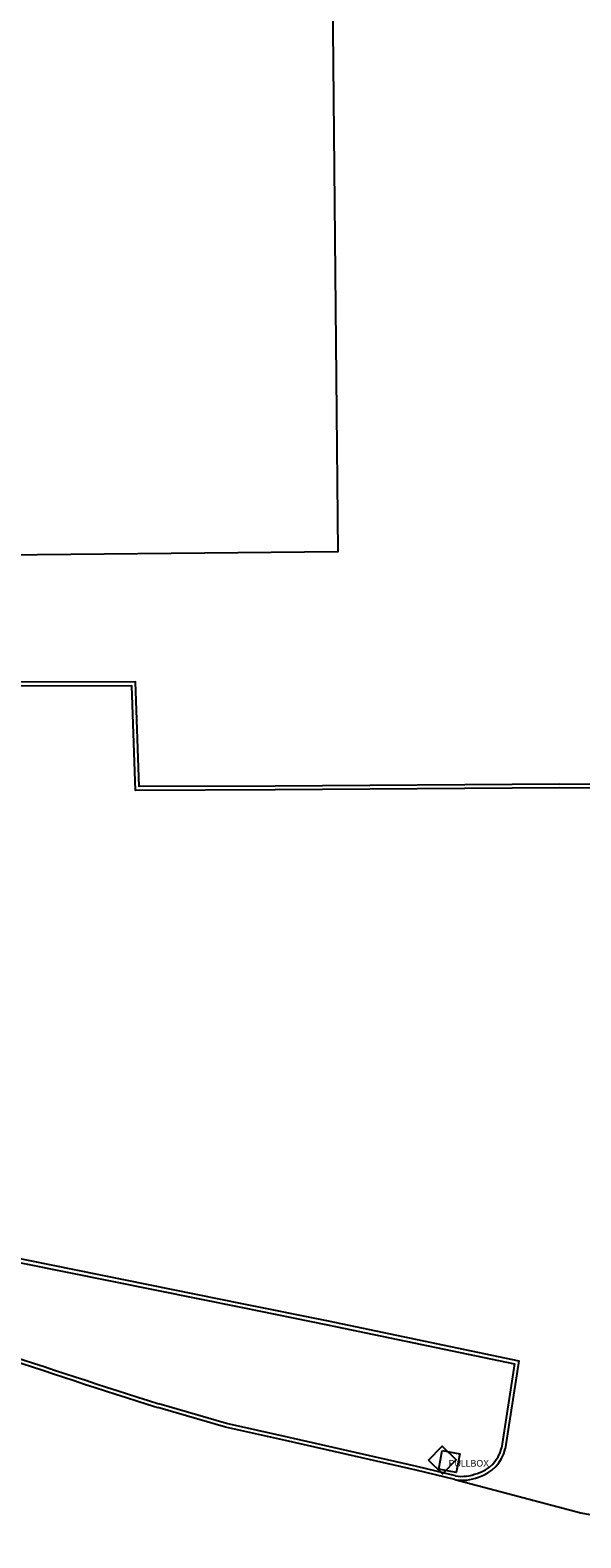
# Model space of a CAD drawing. Extents: x 2145380 to 2156929, y 139568 to 149130.
# Drawn here: x 2151125.7 to 2151210.1, y 145633.5 to 145864.8 of the extents above; entities that cross this region are included whole.
import ezdxf

# ---------------------------------------------------------------- set-up
doc = ezdxf.new("R2010")
doc.units = 0
for name, color, linetype in [('Default', 7, 'Continuous'), ('TOPO_Asphalt', 7, 'Continuous'), ('TOPO_Building', 7, 'Continuous'), ('TOPO_Curb Back', 7, 'Continuous'), ('TOPO_DRAIN_Inlet Grate', 7, 'Continuous'), ('TOPO_Power Pullbox', 7, 'Continuous')]:
    doc.layers.add(name, color=color, linetype=linetype)

# ---------------------------------------------------------------- blocks, each defined once
blk = doc.blocks.new('pulbox')
at = {"layer": 'Default'}
blk.add_lwpolyline([(-5.38, -0.01), (-0.02, 5.42), (5.4, 0.06), (0.05, -5.36), (-5.38, -0.01)], dxfattribs=at)
blk.add_text('PULLBOX', height=2.54, dxfattribs=at).set_placement((2.54, -2.54))

msp = doc.modelspace()

# ---------------------------------------------------------------- linework, layer by layer
at = {"layer": 'TOPO_Asphalt'}
msp.add_lwpolyline([(2151190.79, 145642.47), (2151210.13, 145637.38)], dxfattribs=at)
msp.add_arc((2151248.89, 145831.11), 197.58, 258.687, 271.7273, dxfattribs=at)
at = {"layer": 'TOPO_Building'}
msp.add_lwpolyline([(2151171.94, 145881.01), (2151172.88, 145784.76), (2151111.47, 145784.16), (2151111.23, 145808.23), (2151109.97, 145808.22), (2151109.28, 145880.07), (2151070.88, 145879.7), (2151071.52, 145813.5), (2151007.23, 145812.88), (2151006.64, 145873.96), (2150993.06, 145873.83), (2150992.7, 145910.67), (2151014.52, 145910.88), (2151014.53, 145909.77), (2151156.7, 145911.15), (2151156.99, 145880.87)], close=True, dxfattribs=at)
at = {"layer": 'TOPO_Curb Back'}
for points in [[(2151232.04, 145670.64), (2151232.85, 145679.69), (2151232.77, 145701.33), (2151232.73, 145721.64), (2151232.83, 145748.41), (2151206.88, 145748.55), (2151163.27, 145748.25), (2151141.84, 145748.16), (2151141.29, 145764.21), (2151114.56, 145764.17), (2151114.58, 145767.02)], [(2151232.64, 145670.63), (2151233.45, 145679.66), (2151233.37, 145701.33), (2151233.33, 145721.64), (2151233.43, 145749.01), (2151206.88, 145749.15), (2151163.26, 145748.85), (2151142.42, 145748.76), (2151141.87, 145764.81), (2151115.17, 145764.77), (2151115.18, 145767.01)], [(2151026.47, 145697.22), (2151026.29, 145695.56), (2151069.97, 145686.63), (2151117.91, 145677.02), (2151158.27, 145668.86), (2151171.27, 145666.22), (2151199.97, 145660.21), (2151197.96, 145647.31)], [(2151027.07, 145697.15), (2151026.94, 145696.04), (2151070.09, 145687.22), (2151118.03, 145677.61), (2151158.39, 145669.45), (2151171.39, 145666.81), (2151200.65, 145660.68), (2151198.54, 145647.19)], [(2151190.79, 145642.47), (2151184.86, 145643.9), (2151164.83, 145648.47), (2151155.65, 145650.5), (2151145.26, 145653.51)], [(2151190.91, 145643.06), (2151184.99, 145644.49), (2151164.96, 145649.05), (2151155.8, 145651.08), (2151145.43, 145654.08)]]:
    msp.add_lwpolyline(points, dxfattribs=at)
for centre, radius, start, end in [((2151619.93, 147143.62), 1563.29, 251.34424, 252.3305), ((2151619.98, 147143.75), 1564.02, 251.34439, 252.33073), ((2151192.8, 145648.53), 5.3, 285.7875, 346.6042), ((2151192.8, 145648.53), 5.9, 286.1237, 346.8431), ((2151191.92, 145649.07), 6.7, 260.2905, 292.1084), ((2151191.92, 145649.07), 6.1, 260.4751, 292.4076)]:
    msp.add_arc(centre, radius, start, end, dxfattribs=at)
at = {"layer": 'TOPO_DRAIN_Inlet Grate'}
msp.add_lwpolyline([(2151188.88, 145646.92), (2151191.56, 145646.42), (2151191.02, 145643.58), (2151188.35, 145644.08)], close=True, dxfattribs=at)

# ---------------------------------------------------------------- block references
at = {"layer": 'TOPO_Power Pullbox', "xscale": 0.39370000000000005, "yscale": 0.3937000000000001}
msp.add_blockref('pulbox', (2151188.88, 145645.47), dxfattribs=at)

doc.saveas('drawing.dxf')
